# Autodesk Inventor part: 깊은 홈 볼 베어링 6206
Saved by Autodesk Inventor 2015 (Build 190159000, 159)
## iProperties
Created: 2026-07
Part Number: 깊은 홈 볼 베어링 6206
Material: 일반
Document SubType Name: Modeling
Designer: USER
Density: 1 g/cm^3
Appearance: 기본값
Author: USER
Author: jhkim
Description: 깊은 그루브 볼 베어링
Creation Date: 2026-07-01
Sending System: Autodesk Inventor 2027
Preprocessor: ST-DEVELOPER v20.1
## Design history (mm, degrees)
node "깊은 홈 볼 베어링 62061"
body "Solid1"
node "Solid1_1"
node "Solid1_2"
node "Solid1_3"
node "Solid1_4"
node "Solid1_5"
node "Solid1_6"
node "Solid1_7"
node "Solid1_8"
node "Solid1_9"
node "Solid1_10"
node "기준1"
node "기준2"
node "기준3"
node "기준4"
node "기준5"
node "기준6"
node "기준7"
node "기준8"
node "기준9"
node "기준10"
node "기준11"
